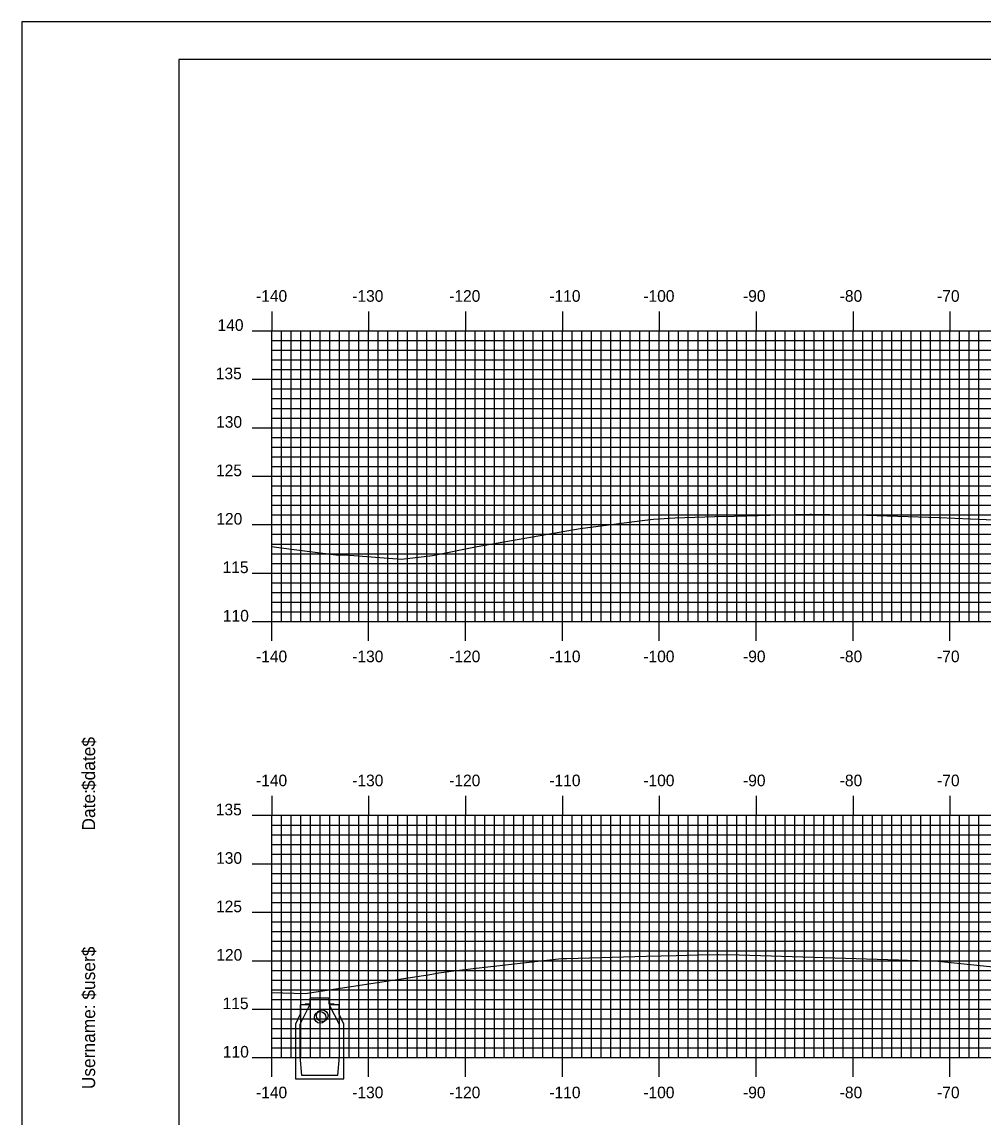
# Model space of a CAD drawing. Extents: x 852540 to 852884, y 364661 to 364881.
# Drawn here: x 852540.5 to 852639.7, y 364768.2 to 364881.3 of the extents above; entities that cross this region are included whole.
import ezdxf

# ---------------------------------------------------------------- set-up
doc = ezdxf.new("R2010")
doc.units = 0
for name, color, linetype in [('BORDER', 7, 'Continuous'), ('H_V ANNOTATION', 7, 'Continuous'), ('M_Roadway_Centerline', 7, 'Continuous'), ('MAJOR', 7, 'Continuous'), ('MINOR', 7, 'Continuous'), ('PLOT BOUNDARY', 7, 'Continuous'), ('S_Drainage_CB', 7, 'Continuous'), ('S_Drainage_Invert', 7, 'Continuous'), ('S_Roadway_Centerline', 7, 'Continuous')]:
    doc.layers.add(name, color=color, linetype=linetype)

msp = doc.modelspace()

# ---------------------------------------------------------------- linework, layer by layer
at = {"layer": 'BORDER'}
msp.add_lwpolyline([(852556.67, 364667.37), (852876.67, 364667.37), (852876.67, 364877.37), (852556.67, 364877.37)], close=True, dxfattribs=at)
at = {"layer": 'MAJOR'}
for p, q in [((852566.27, 364851.37), (852566.27, 364849.37)), ((852576.27, 364851.37), (852576.27, 364849.37)), ((852586.27, 364851.37), (852586.27, 364849.37)), ((852596.27, 364851.37), (852596.27, 364849.37)), ((852606.27, 364851.37), (852606.27, 364849.37)), ((852616.27, 364851.37), (852616.27, 364849.37)), ((852626.27, 364851.37), (852626.27, 364849.37)), ((852636.27, 364851.37), (852636.27, 364849.37)), ((852564.26, 364849.37), (852566.27, 364849.37)), ((852566.27, 364849.37), (852846.27, 364849.37)), ((852566.27, 364819.37), (852566.27, 364849.37)), ((852566.27, 364819.37), (852566.27, 364849.37)), ((852566.27, 364849.37), (852846.27, 364849.37)), ((852576.27, 364819.37), (852576.27, 364849.37)), ((852586.27, 364819.37), (852586.27, 364849.37)), ((852596.27, 364819.37), (852596.27, 364849.37)), ((852606.27, 364819.37), (852606.27, 364849.37)), ((852616.27, 364819.37), (852616.27, 364849.37)), ((852626.27, 364819.37), (852626.27, 364849.37)), ((852636.27, 364819.37), (852636.27, 364849.37)), ((852564.26, 364844.37), (852566.27, 364844.37)), ((852566.27, 364844.37), (852846.27, 364844.37)), ((852564.26, 364839.37), (852566.27, 364839.37)), ((852566.27, 364839.37), (852846.27, 364839.37)), ((852564.26, 364834.37), (852566.27, 364834.37)), ((852566.27, 364834.37), (852846.27, 364834.37)), ((852564.26, 364829.37), (852566.27, 364829.37)), ((852566.27, 364829.37), (852846.27, 364829.37)), ((852564.26, 364824.37), (852566.27, 364824.37)), ((852566.27, 364824.37), (852846.27, 364824.37)), ((852564.26, 364819.37), (852566.27, 364819.37)), ((852566.27, 364819.37), (852846.27, 364819.37)), ((852566.27, 364819.37), (852846.27, 364819.37)), ((852566.27, 364817.37), (852566.27, 364819.37)), ((852576.27, 364817.37), (852576.27, 364819.37)), ((852586.27, 364817.37), (852586.27, 364819.37)), ((852596.27, 364817.37), (852596.27, 364819.37)), ((852606.27, 364817.37), (852606.27, 364819.37)), ((852616.27, 364817.37), (852616.27, 364819.37)), ((852626.27, 364817.37), (852626.27, 364819.37)), ((852636.27, 364817.37), (852636.27, 364819.37)), ((852566.27, 364801.37), (852566.27, 364799.37)), ((852576.27, 364801.37), (852576.27, 364799.37)), ((852586.27, 364801.37), (852586.27, 364799.37)), ((852596.27, 364801.37), (852596.27, 364799.37)), ((852606.27, 364801.37), (852606.27, 364799.37)), ((852616.27, 364801.37), (852616.27, 364799.37)), ((852626.27, 364801.37), (852626.27, 364799.37)), ((852636.27, 364801.37), (852636.27, 364799.37)), ((852564.26, 364799.37), (852566.27, 364799.37)), ((852566.27, 364799.37), (852846.27, 364799.37)), ((852566.27, 364774.37), (852566.27, 364799.37)), ((852566.27, 364774.37), (852566.27, 364799.37)), ((852566.27, 364799.37), (852846.27, 364799.37)), ((852576.27, 364774.37), (852576.27, 364799.37)), ((852586.27, 364774.37), (852586.27, 364799.37)), ((852596.27, 364774.37), (852596.27, 364799.37)), ((852606.27, 364774.37), (852606.27, 364799.37)), ((852616.27, 364774.37), (852616.27, 364799.37)), ((852626.27, 364774.37), (852626.27, 364799.37)), ((852636.27, 364774.37), (852636.27, 364799.37)), ((852564.26, 364794.37), (852566.27, 364794.37)), ((852566.27, 364794.37), (852846.27, 364794.37)), ((852564.26, 364789.37), (852566.27, 364789.37)), ((852566.27, 364789.37), (852846.27, 364789.37)), ((852564.26, 364784.37), (852566.27, 364784.37)), ((852566.27, 364784.37), (852846.27, 364784.37)), ((852564.26, 364779.37), (852566.27, 364779.37)), ((852566.27, 364779.37), (852846.27, 364779.37)), ((852564.26, 364774.37), (852566.27, 364774.37)), ((852566.27, 364774.37), (852846.27, 364774.37)), ((852566.27, 364774.37), (852846.27, 364774.37)), ((852566.27, 364772.37), (852566.27, 364774.37)), ((852576.27, 364772.37), (852576.27, 364774.37)), ((852586.27, 364772.37), (852586.27, 364774.37)), ((852596.27, 364772.37), (852596.27, 364774.37)), ((852606.27, 364772.37), (852606.27, 364774.37)), ((852616.27, 364772.37), (852616.27, 364774.37)), ((852626.27, 364772.37), (852626.27, 364774.37)), ((852636.27, 364772.37), (852636.27, 364774.37))]:
    msp.add_line(p, q, dxfattribs=at)
at = {"layer": 'MINOR'}
for p, q in [((852567.27, 364819.37), (852567.27, 364849.37)), ((852568.27, 364819.37), (852568.27, 364849.37)), ((852569.27, 364819.37), (852569.27, 364849.37)), ((852570.27, 364819.37), (852570.27, 364849.37)), ((852571.27, 364819.37), (852571.27, 364849.37)), ((852572.27, 364819.37), (852572.27, 364849.37)), ((852573.27, 364819.37), (852573.27, 364849.37)), ((852574.27, 364819.37), (852574.27, 364849.37)), ((852575.27, 364819.37), (852575.27, 364849.37)), ((852577.27, 364819.37), (852577.27, 364849.37)), ((852578.27, 364819.37), (852578.27, 364849.37)), ((852579.27, 364819.37), (852579.27, 364849.37)), ((852580.27, 364819.37), (852580.27, 364849.37)), ((852581.27, 364819.37), (852581.27, 364849.37)), ((852582.27, 364819.37), (852582.27, 364849.37)), ((852583.27, 364819.37), (852583.27, 364849.37)), ((852584.27, 364819.37), (852584.27, 364849.37)), ((852585.27, 364819.37), (852585.27, 364849.37)), ((852587.27, 364819.37), (852587.27, 364849.37)), ((852588.27, 364819.37), (852588.27, 364849.37)), ((852589.27, 364819.37), (852589.27, 364849.37)), ((852590.27, 364819.37), (852590.27, 364849.37)), ((852591.27, 364819.37), (852591.27, 364849.37)), ((852592.27, 364819.37), (852592.27, 364849.37)), ((852593.27, 364819.37), (852593.27, 364849.37)), ((852594.27, 364819.37), (852594.27, 364849.37)), ((852595.27, 364819.37), (852595.27, 364849.37)), ((852597.27, 364819.37), (852597.27, 364849.37)), ((852598.27, 364819.37), (852598.27, 364849.37)), ((852599.27, 364819.37), (852599.27, 364849.37)), ((852600.27, 364819.37), (852600.27, 364849.37)), ((852601.27, 364819.37), (852601.27, 364849.37)), ((852602.27, 364819.37), (852602.27, 364849.37)), ((852603.27, 364819.37), (852603.27, 364849.37)), ((852604.27, 364819.37), (852604.27, 364849.37)), ((852605.27, 364819.37), (852605.27, 364849.37)), ((852607.27, 364819.37), (852607.27, 364849.37)), ((852608.27, 364819.37), (852608.27, 364849.37)), ((852609.27, 364819.37), (852609.27, 364849.37)), ((852610.27, 364819.37), (852610.27, 364849.37)), ((852611.27, 364819.37), (852611.27, 364849.37)), ((852612.27, 364819.37), (852612.27, 364849.37)), ((852613.27, 364819.37), (852613.27, 364849.37)), ((852614.27, 364819.37), (852614.27, 364849.37)), ((852615.27, 364819.37), (852615.27, 364849.37)), ((852617.27, 364819.37), (852617.27, 364849.37)), ((852618.27, 364819.37), (852618.27, 364849.37)), ((852619.27, 364819.37), (852619.27, 364849.37)), ((852620.27, 364819.37), (852620.27, 364849.37)), ((852621.27, 364819.37), (852621.27, 364849.37)), ((852622.27, 364819.37), (852622.27, 364849.37)), ((852623.27, 364819.37), (852623.27, 364849.37)), ((852624.27, 364819.37), (852624.27, 364849.37)), ((852625.27, 364819.37), (852625.27, 364849.37)), ((852627.27, 364819.37), (852627.27, 364849.37)), ((852628.27, 364819.37), (852628.27, 364849.37)), ((852629.27, 364819.37), (852629.27, 364849.37)), ((852630.27, 364819.37), (852630.27, 364849.37)), ((852631.27, 364819.37), (852631.27, 364849.37)), ((852632.27, 364819.37), (852632.27, 364849.37)), ((852633.27, 364819.37), (852633.27, 364849.37)), ((852634.27, 364819.37), (852634.27, 364849.37)), ((852635.27, 364819.37), (852635.27, 364849.37)), ((852637.27, 364819.37), (852637.27, 364849.37)), ((852638.27, 364819.37), (852638.27, 364849.37)), ((852639.27, 364819.37), (852639.27, 364849.37)), ((852566.27, 364848.37), (852846.27, 364848.37)), ((852566.27, 364848.37), (852568.27, 364848.37)), ((852566.27, 364847.37), (852846.27, 364847.37)), ((852566.27, 364847.37), (852568.27, 364847.37)), ((852566.27, 364846.37), (852846.27, 364846.37)), ((852566.27, 364846.37), (852568.27, 364846.37)), ((852566.27, 364845.37), (852846.27, 364845.37)), ((852566.27, 364845.37), (852568.27, 364845.37)), ((852566.27, 364843.37), (852846.27, 364843.37)), ((852566.27, 364843.37), (852568.27, 364843.37)), ((852566.27, 364842.37), (852846.27, 364842.37)), ((852566.27, 364842.37), (852568.27, 364842.37)), ((852566.27, 364841.37), (852846.27, 364841.37)), ((852566.27, 364841.37), (852568.27, 364841.37)), ((852566.27, 364840.37), (852846.27, 364840.37)), ((852566.27, 364840.37), (852568.27, 364840.37)), ((852566.27, 364838.37), (852846.27, 364838.37)), ((852566.27, 364838.37), (852568.27, 364838.37)), ((852566.27, 364837.37), (852846.27, 364837.37)), ((852566.27, 364837.37), (852568.27, 364837.37)), ((852566.27, 364836.37), (852846.27, 364836.37)), ((852566.27, 364836.37), (852568.27, 364836.37)), ((852566.27, 364835.37), (852846.27, 364835.37)), ((852566.27, 364835.37), (852568.27, 364835.37)), ((852566.27, 364833.37), (852846.27, 364833.37)), ((852566.27, 364833.37), (852568.27, 364833.37)), ((852566.27, 364832.37), (852846.27, 364832.37)), ((852566.27, 364832.37), (852568.27, 364832.37)), ((852566.27, 364831.37), (852846.27, 364831.37)), ((852566.27, 364831.37), (852568.27, 364831.37)), ((852566.27, 364830.37), (852846.27, 364830.37)), ((852566.27, 364830.37), (852568.27, 364830.37)), ((852566.27, 364828.37), (852846.27, 364828.37)), ((852566.27, 364828.37), (852568.27, 364828.37)), ((852566.27, 364827.37), (852846.27, 364827.37)), ((852566.27, 364827.37), (852568.27, 364827.37)), ((852566.27, 364826.37), (852846.27, 364826.37)), ((852566.27, 364826.37), (852568.27, 364826.37)), ((852566.27, 364825.37), (852846.27, 364825.37)), ((852566.27, 364825.37), (852568.27, 364825.37)), ((852566.27, 364823.37), (852846.27, 364823.37)), ((852566.27, 364823.37), (852568.27, 364823.37)), ((852566.27, 364822.37), (852846.27, 364822.37)), ((852566.27, 364822.37), (852568.27, 364822.37)), ((852566.27, 364821.37), (852846.27, 364821.37)), ((852566.27, 364821.37), (852568.27, 364821.37)), ((852566.27, 364820.37), (852846.27, 364820.37)), ((852566.27, 364820.37), (852568.27, 364820.37)), ((852567.27, 364774.37), (852567.27, 364799.37)), ((852568.27, 364774.37), (852568.27, 364799.37)), ((852569.27, 364774.37), (852569.27, 364799.37)), ((852570.27, 364774.37), (852570.27, 364799.37)), ((852571.27, 364774.37), (852571.27, 364799.37)), ((852572.27, 364774.37), (852572.27, 364799.37)), ((852573.27, 364774.37), (852573.27, 364799.37)), ((852574.27, 364774.37), (852574.27, 364799.37)), ((852575.27, 364774.37), (852575.27, 364799.37)), ((852577.27, 364774.37), (852577.27, 364799.37)), ((852578.27, 364774.37), (852578.27, 364799.37)), ((852579.27, 364774.37), (852579.27, 364799.37)), ((852580.27, 364774.37), (852580.27, 364799.37)), ((852581.27, 364774.37), (852581.27, 364799.37)), ((852582.27, 364774.37), (852582.27, 364799.37)), ((852583.27, 364774.37), (852583.27, 364799.37)), ((852584.27, 364774.37), (852584.27, 364799.37)), ((852585.27, 364774.37), (852585.27, 364799.37)), ((852587.27, 364774.37), (852587.27, 364799.37)), ((852588.27, 364774.37), (852588.27, 364799.37)), ((852589.27, 364774.37), (852589.27, 364799.37)), ((852590.27, 364774.37), (852590.27, 364799.37)), ((852591.27, 364774.37), (852591.27, 364799.37)), ((852592.27, 364774.37), (852592.27, 364799.37)), ((852593.27, 364774.37), (852593.27, 364799.37)), ((852594.27, 364774.37), (852594.27, 364799.37)), ((852595.27, 364774.37), (852595.27, 364799.37)), ((852597.27, 364774.37), (852597.27, 364799.37)), ((852598.27, 364774.37), (852598.27, 364799.37)), ((852599.27, 364774.37), (852599.27, 364799.37)), ((852600.27, 364774.37), (852600.27, 364799.37)), ((852601.27, 364774.37), (852601.27, 364799.37)), ((852602.27, 364774.37), (852602.27, 364799.37)), ((852603.27, 364774.37), (852603.27, 364799.37)), ((852604.27, 364774.37), (852604.27, 364799.37)), ((852605.27, 364774.37), (852605.27, 364799.37)), ((852607.27, 364774.37), (852607.27, 364799.37)), ((852608.27, 364774.37), (852608.27, 364799.37)), ((852609.27, 364774.37), (852609.27, 364799.37)), ((852610.27, 364774.37), (852610.27, 364799.37)), ((852611.27, 364774.37), (852611.27, 364799.37)), ((852612.27, 364774.37), (852612.27, 364799.37)), ((852613.27, 364774.37), (852613.27, 364799.37)), ((852614.27, 364774.37), (852614.27, 364799.37)), ((852615.27, 364774.37), (852615.27, 364799.37)), ((852617.27, 364774.37), (852617.27, 364799.37)), ((852618.27, 364774.37), (852618.27, 364799.37)), ((852619.27, 364774.37), (852619.27, 364799.37)), ((852620.27, 364774.37), (852620.27, 364799.37)), ((852621.27, 364774.37), (852621.27, 364799.37)), ((852622.27, 364774.37), (852622.27, 364799.37)), ((852623.27, 364774.37), (852623.27, 364799.37)), ((852624.27, 364774.37), (852624.27, 364799.37)), ((852625.27, 364774.37), (852625.27, 364799.37)), ((852627.27, 364774.37), (852627.27, 364799.37)), ((852628.27, 364774.37), (852628.27, 364799.37)), ((852629.27, 364774.37), (852629.27, 364799.37)), ((852630.27, 364774.37), (852630.27, 364799.37)), ((852631.27, 364774.37), (852631.27, 364799.37)), ((852632.27, 364774.37), (852632.27, 364799.37)), ((852633.27, 364774.37), (852633.27, 364799.37)), ((852634.27, 364774.37), (852634.27, 364799.37)), ((852635.27, 364774.37), (852635.27, 364799.37)), ((852637.27, 364774.37), (852637.27, 364799.37)), ((852638.27, 364774.37), (852638.27, 364799.37)), ((852639.27, 364774.37), (852639.27, 364799.37)), ((852566.27, 364798.37), (852846.27, 364798.37)), ((852566.27, 364798.37), (852568.27, 364798.37)), ((852566.27, 364797.37), (852846.27, 364797.37)), ((852566.27, 364797.37), (852568.27, 364797.37)), ((852566.27, 364796.37), (852846.27, 364796.37)), ((852566.27, 364796.37), (852568.27, 364796.37)), ((852566.27, 364795.37), (852846.27, 364795.37)), ((852566.27, 364795.37), (852568.27, 364795.37)), ((852566.27, 364793.37), (852846.27, 364793.37)), ((852566.27, 364793.37), (852568.27, 364793.37)), ((852566.27, 364792.37), (852846.27, 364792.37)), ((852566.27, 364792.37), (852568.27, 364792.37)), ((852566.27, 364791.37), (852846.27, 364791.37)), ((852566.27, 364791.37), (852568.27, 364791.37)), ((852566.27, 364790.37), (852846.27, 364790.37)), ((852566.27, 364790.37), (852568.27, 364790.37)), ((852566.27, 364788.37), (852846.27, 364788.37)), ((852566.27, 364788.37), (852568.27, 364788.37)), ((852566.27, 364787.37), (852846.27, 364787.37)), ((852566.27, 364787.37), (852568.27, 364787.37)), ((852566.27, 364786.37), (852846.27, 364786.37)), ((852566.27, 364786.37), (852568.27, 364786.37)), ((852566.27, 364785.37), (852846.27, 364785.37)), ((852566.27, 364785.37), (852568.27, 364785.37)), ((852566.27, 364783.37), (852846.27, 364783.37)), ((852566.27, 364783.37), (852568.27, 364783.37)), ((852566.27, 364782.37), (852846.27, 364782.37)), ((852566.27, 364782.37), (852568.27, 364782.37)), ((852566.27, 364781.37), (852846.27, 364781.37)), ((852566.27, 364781.37), (852568.27, 364781.37)), ((852566.27, 364780.37), (852846.27, 364780.37)), ((852566.27, 364780.37), (852568.27, 364780.37)), ((852566.27, 364778.37), (852846.27, 364778.37)), ((852566.27, 364778.37), (852568.27, 364778.37)), ((852566.27, 364777.37), (852846.27, 364777.37)), ((852566.27, 364777.37), (852568.27, 364777.37)), ((852566.27, 364776.37), (852846.27, 364776.37)), ((852566.27, 364776.37), (852568.27, 364776.37)), ((852566.27, 364775.37), (852846.27, 364775.37)), ((852566.27, 364775.37), (852568.27, 364775.37))]:
    msp.add_line(p, q, dxfattribs=at)
at = {"layer": 'PLOT BOUNDARY'}
msp.add_lwpolyline([(852540.48, 364661.25), (852880.48, 364661.25), (852880.48, 364881.25), (852540.48, 364881.25)], close=True, dxfattribs=at)
at = {"layer": 'S_Drainage_CB'}
for p, q in [((852569.22, 364778.85), (852568.73, 364777.83)), ((852570.21, 364779.83), (852569.22, 364779.83)), ((852569.22, 364779.83), (852569.22, 364778.85)), ((852569.22, 364777.83), (852570.21, 364779.83)), ((852573.23, 364779.83), (852572.21, 364779.83)), ((852572.21, 364779.83), (852573.23, 364777.83)), ((852573.23, 364778.85), (852573.23, 364779.83)), ((852573.72, 364777.83), (852573.23, 364778.85)), ((852568.73, 364777.83), (852568.73, 364772.19)), ((852569.22, 364774.51), (852569.22, 364777.83)), ((852573.23, 364777.83), (852573.23, 364774.51)), ((852573.72, 364772.19), (852573.72, 364777.83)), ((852569.39, 364772.51), (852569.22, 364774.51)), ((852573.23, 364774.51), (852573.06, 364772.51)), ((852568.73, 364772.19), (852573.72, 364772.19)), ((852573.06, 364772.51), (852569.39, 364772.51))]:
    msp.add_line(p, q, dxfattribs=at)
msp.add_lwpolyline([(852572.7, 364779.87), (852572.21, 364779.87), (852572.21, 364780.49), (852570.21, 364780.49), (852570.21, 364779.87), (852569.72, 364779.87)], dxfattribs=at)
at = {"layer": 'S_Drainage_Invert'}
for centre in [(852571.27, 364778.52), (852571.48, 364778.69)]:
    msp.add_circle(centre, 0.6, dxfattribs=at)
at = {"layer": 'S_Roadway_Centerline'}
for points in [[(852566.27, 364827.11), (852567.23, 364826.98), (852573.15, 364826.22), (852573.84, 364826.24), (852579.68, 364825.81), (852582.87, 364826.2), (852587.46, 364827.12), (852598.1, 364828.98), (852604.77, 364829.82), (852605.66, 364829.95), (852607.89, 364830.08), (852612, 364830.2), (852614.01, 364830.26), (852620.2, 364830.43), (852621.8, 364830.46), (852621.97, 364830.44), (852627.68, 364830.33), (852635.17, 364830.09), (852643.25, 364829.77)], [(852566.27, 364781.1), (852569.71, 364781), (852581.93, 364782.83), (852582.4, 364782.9), (852583.51, 364783.12), (852584.78, 364783.28), (852587.06, 364783.55), (852596.17, 364784.59), (852596.74, 364784.61), (852604.92, 364784.82), (852608.03, 364784.91), (852610.23, 364784.98), (852612.28, 364785.02), (852612.39, 364785.01), (852614.52, 364784.97), (852630.96, 364784.46), (852631.89, 364784.43), (852635.07, 364784.32), (852642.74, 364783.53)]]:
    msp.add_lwpolyline(points, dxfattribs=at)

# ---------------------------------------------------------------- texts
at = {"layer": 'BORDER'}
for s, p in [('$date$', (852548.04, 364801.98)), ('Date:', (852548.04, 364797.8)), ('$user$', (852548.04, 364780.35)), ('Username:', (852548.04, 364771.11))]:
    msp.add_text(s, height=1.339, rotation=90, dxfattribs=at).set_placement(p)
at = {"layer": 'H_V ANNOTATION'}
for s, p in [('-140', (852564.65, 364852.37)), ('-130', (852574.58, 364852.37)), ('-120', (852584.59, 364852.37)), ('-110', (852594.93, 364852.37)), ('-100', (852604.63, 364852.37)), ('-90', (852614.92, 364852.37)), ('-80', (852624.9, 364852.37)), ('-70', (852634.95, 364852.37)), ('140', (852560.68, 364849.37)), ('135', (852560.5, 364844.37)), ('130', (852560.53, 364839.37)), ('125', (852560.52, 364834.37)), ('120', (852560.55, 364829.37)), ('115', (852561.2, 364824.37)), ('110', (852561.23, 364819.37)), ('-140', (852564.65, 364815.17)), ('-130', (852574.58, 364815.17)), ('-120', (852584.59, 364815.17)), ('-110', (852594.93, 364815.17)), ('-100', (852604.63, 364815.17)), ('-90', (852614.92, 364815.17)), ('-80', (852624.9, 364815.17)), ('-70', (852634.95, 364815.17)), ('-140', (852564.65, 364802.37)), ('-130', (852574.58, 364802.37)), ('-120', (852584.59, 364802.37)), ('-110', (852594.93, 364802.37)), ('-100', (852604.63, 364802.37)), ('-90', (852614.92, 364802.37)), ('-80', (852624.9, 364802.37)), ('-70', (852634.95, 364802.37)), ('135', (852560.5, 364799.37)), ('130', (852560.53, 364794.37)), ('125', (852560.52, 364789.37)), ('120', (852560.55, 364784.37)), ('115', (852561.2, 364779.37)), ('110', (852561.23, 364774.37)), ('-140', (852564.65, 364770.17)), ('-130', (852574.58, 364770.17)), ('-120', (852584.59, 364770.17)), ('-110', (852594.93, 364770.17)), ('-100', (852604.63, 364770.17)), ('-90', (852614.92, 364770.17)), ('-80', (852624.9, 364770.17)), ('-70', (852634.95, 364770.17))]:
    msp.add_text(s, height=1.2, dxfattribs=at).set_placement(p)
at = {"layer": 'M_Roadway_Centerline'}
for s, p in [('C', (852621.8, 364830.46)), ('L', (852621.8, 364830.45)), ('C', (852612.28, 364785.02)), ('L', (852612.28, 364785.01))]:
    msp.add_text(s, height=0.0146, dxfattribs=at).set_placement(p)
at = {"layer": 'MAJOR'}
for p in [(852566.26, 364819.37), (852566.26, 364774.37)]:
    msp.add_text('-', height=0.012, dxfattribs=at).set_placement(p)

doc.saveas('drawing.dxf')
